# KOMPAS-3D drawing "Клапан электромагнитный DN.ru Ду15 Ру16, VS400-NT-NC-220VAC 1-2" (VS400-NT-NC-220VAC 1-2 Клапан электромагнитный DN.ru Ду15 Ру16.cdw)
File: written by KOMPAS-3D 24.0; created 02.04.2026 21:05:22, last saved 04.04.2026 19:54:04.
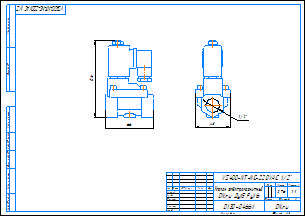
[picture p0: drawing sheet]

Document properties: c3d_UniqueCompID: ef56311e-7521-43dc-8291-0e6108b3d81d; Обозначение: VS400-ET-NC-220VAC 1-2; Наименование: Клапан электромагнитный DN.ru Ду15 Ру16; Автор: artio; Класс точности: c; Знак неуказанной шероховатости: Шероховатость не задана; Рассекать на разрезах: Да; c3d_UniqueCompID: ef56311e-7521-43dc-8291-0e6108b3d81d; Обозначение: VS400-ET-NC-220VAC 3-8; Наименование: Клапан электромагнитный DN.ru Ду10 Ру16; Автор: artio; Класс точности: c; Знак неуказанной шероховатости: Шероховатость не задана; Рассекать на разрезах: Да; Автор: artio; Форматы листов документа: A3; Полное имя файла: VS400-NT-NC-220VAC 1-2 Клапан электромагнитный DN.ru Ду15 Ру16.m3d; Масса: 0.759; Наименование: Клапан электромагнитный DN.ru Ду15 Ру16; Количество листов документа: 1; Примечание: D130-04661

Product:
- Body: Тело 1  | qty 1
    Масса: 1.030062
- Part/product: Клапан электромагнитный DN.ru Ду15 Ру16  | designation VS400-NT-NC-220VAC 1-2
    Масса: 0.759
    Раздел спецификации: Прочие изделия
    Примечание: D130-04661
    additional columns: ef56311e-7521-43dc-8291-0e6108b3d81d; VS400-ET-NC-220VAC 1-2; artio; c; Шероховатость не задана; Да

Views: Вид 1, Спереди, Проекционный вид 2
Referenced files in C:\Users\artio\OneDrive\Рабочий стол\Клапан электромагнитный DN.ru VS4x-xT-NC-x\DN10\: VS400-ET-NC-220VAC 3-8 Клапан электромагнитный DN.ru Ду10 Ру16.m3d, VS400-ET-NC-220VAC 3-8 Клапан электромагнитный DN.ru Ду10 Ру16.cdw
Referenced files in C:\Users\artio\OneDrive\Рабочий стол\Клапан электромагнитный DN.ru\VS400-NT-NC\VS400-NT-NC-220VAC\: VS400-NT-NC-220VAC 1-2 Клапан электромагнитный DN.ru Ду15 Ру16.m3d
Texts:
  VS400-NT-NC-220VAC 1-2
  Линейный размер
  Клапан электромагнитный
  DN.ru Ду15 Ру16
  VS400-NT-NC-220VAC 1/2"
  VS400-NT-NC-220VAC 1/2"-
  Клапан электромагнитный DN.ru Ду15 Ру16
  VS400-NT-NC-220VAC 1-2 Клапан электромагнитный DN.ru Ду15 Ру16
Dimensions and other numbers on the sheet: 0; 3; 2; 4; 48; 1/2"; 66; 106; 1:1; 1; 0,76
